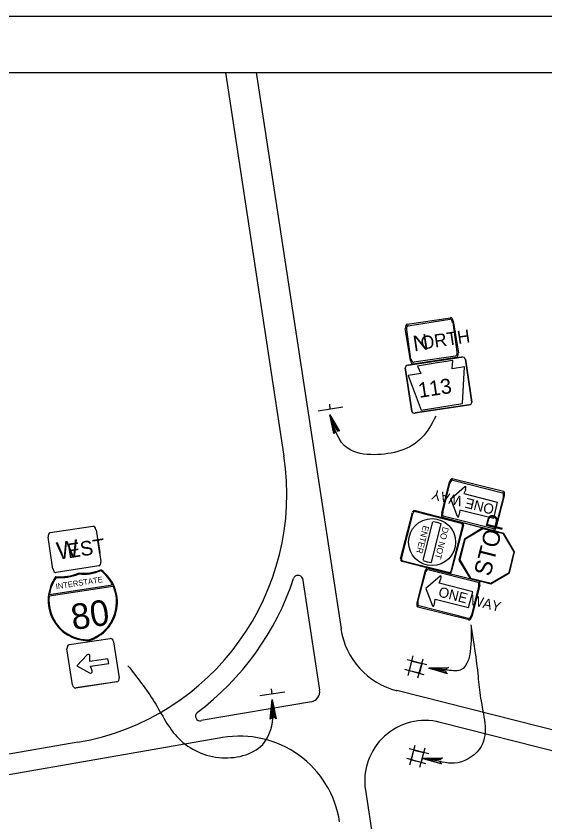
# Model space of a CAD drawing. Extents: x 640994 to 644422, y 298458 to 299646.
# Drawn here: x 642997.9 to 643138.7, y 299430.9 to 299645.6 of the extents above; entities that cross this region are included whole.
import ezdxf

# ---------------------------------------------------------------- set-up
doc = ezdxf.new("R2010")
doc.units = 0
for name, color, linetype in [('1', 7, 'Continuous'), ('2', 7, 'Continuous'), ('XCS-GRID-MIN', 7, 'Continuous')]:
    doc.layers.add(name, color=color, linetype=linetype)

msp = doc.modelspace()

# ---------------------------------------------------------------- linework, layer by layer
at = {"layer": '1'}
msp.add_line((642716.31, 299630.63), (643502.31, 299630.63), dxfattribs=at)
at = {"layer": '2'}
for p, q in [((643053.69, 299630.63), (643069.19, 299528.38)), ((643061.81, 299630.63), (643084.44, 299482.38)), ((643102.06, 299563.5), (643113.56, 299565.25)), ((643102.31, 299563.13), (643113.44, 299564.88)), ((643102.94, 299553.88), (643101.56, 299562.38)), ((643114.19, 299564), (643115.31, 299556.13)), ((643114.31, 299564.38), (643115.69, 299555.88)), ((643103.06, 299554.25), (643101.94, 299562.13)), ((643108.69, 299559.13), (643108.69, 299559.13)), ((643102.31, 299552.63), (643116.56, 299554.75)), ((643116.56, 299554.75), (643102.31, 299552.63)), ((643115.19, 299554.63), (643103.69, 299552.88)), ((643114.94, 299555), (643103.81, 299553.38)), ((643114.19, 299553.88), (643109.56, 299553.13)), ((643114.06, 299551.63), (643114.19, 299553.88)), ((643117.56, 299554.25), (643119.31, 299542.75)), ((643119.31, 299542.75), (643117.56, 299554.25)), ((643103.31, 299540.38), (643101.56, 299551.88)), ((643101.56, 299551.88), (643103.31, 299540.38)), ((643102.31, 299552.63), (643102.31, 299552.63)), ((643109.56, 299553.13), (643104.81, 299552.38)), ((643104.81, 299552.38), (643105.69, 299550.38)), ((643117.31, 299552.13), (643114.06, 299551.63)), ((643116.81, 299542.38), (643117.31, 299552.13)), ((643105.69, 299550.38), (643102.31, 299549.88)), ((643102.31, 299549.88), (643105.81, 299540.63)), ((643110.44, 299547.25), (643110.44, 299547.25)), ((643110.44, 299547.25), (643110.44, 299547.25)), ((643084.94, 299541.38), (643078.31, 299540.38)), ((643081.56, 299540.88), (643081.44, 299542.25)), ((643118.56, 299542), (643104.19, 299539.88)), ((643104.19, 299539.88), (643118.56, 299542)), ((643105.81, 299540.63), (643116.81, 299542.38)), ((643114.06, 299522.38), (643127.69, 299519)), ((643114.19, 299522), (643127.44, 299518.63)), ((643111.31, 299513.13), (643113.31, 299521.5)), ((643111.56, 299513.38), (643113.44, 299521.13)), ((643113.69, 299517), (643117.44, 299520.25)), ((643117.69, 299519.5), (643117.19, 299518.38)), ((643117.19, 299518.38), (643126.06, 299516.13)), ((643127.69, 299517.5), (643125.69, 299509.75)), ((643127.94, 299517.75), (643125.81, 299509.5)), ((643115.44, 299512.25), (643113.69, 299517)), ((643119.56, 299515.5), (643119.56, 299515.5)), ((643126.06, 299516.13), (643125.06, 299511.75)), ((643100.31, 299501), (643103.44, 299513.38)), ((643100.56, 299501), (643103.69, 299513.25)), ((643104.19, 299513.88), (643116.69, 299510.63)), ((643104.31, 299513.63), (643116.44, 299510.5)), ((643116.06, 299514), (643115.94, 299512.88)), ((643125.06, 299511.75), (643116.06, 299514)), ((643106.31, 299500.63), (643108.94, 299510.88)), ((643125.06, 299508.5), (643111.44, 299512)), ((643125.06, 299509), (643111.69, 299512.38)), ((643006.94, 299508), (643018.31, 299509.75)), ((643019.19, 299508.75), (643020.44, 299500.25)), ((643111.06, 299510.38), (643108.44, 299500)), ((643116.81, 299509.88), (643113.69, 299497.75)), ((643117.06, 299510), (643113.81, 299497.5)), ((643007.69, 299498.25), (643006.44, 299506.75)), ((643108.69, 299505.5), (643108.69, 299505.5)), ((643013.44, 299503.5), (643013.44, 299503.5)), ((643113.19, 299497.13), (643100.69, 299500.25)), ((643113.06, 299497.38), (643100.94, 299500.38)), ((643123.31, 299501.75), (643123.31, 299501.75)), ((643019.94, 299499.13), (643008.56, 299497.38)), ((643107.56, 299498.5), (643121.19, 299495.13)), ((643107.56, 299498.13), (643120.94, 299494.75)), ((643008.56, 299496), (643008.56, 299496)), ((643014.56, 299497), (643014.56, 299497)), ((643020.44, 299497.88), (643020.44, 299497.88)), ((643074.19, 299495.88), (643078.69, 299466)), ((643104.69, 299489.25), (643106.81, 299497.63)), ((643104.94, 299489.63), (643106.94, 299497.25)), ((643110.81, 299496.38), (643107.06, 299493.13)), ((643023.56, 299494), (643006.69, 299491.38)), ((643006.69, 299491.13), (643023.69, 299493.75)), ((643110.56, 299494.5), (643111.06, 299495.63)), ((643119.56, 299492.25), (643110.56, 299494.5)), ((643121.06, 299493.63), (643119.19, 299486)), ((643121.44, 299494), (643119.31, 299485.63)), ((643107.06, 299493.13), (643108.81, 299488.5)), ((643113.06, 299491.63), (643113.06, 299491.63)), ((643113.06, 299491.63), (643113.06, 299491.63)), ((643118.44, 299488), (643119.56, 299492.25)), ((643109.31, 299489), (643109.56, 299490.25)), ((643109.56, 299490.25), (643118.44, 299488)), ((643015.81, 299488.25), (643015.81, 299488.25)), ((643118.56, 299484.75), (643104.94, 299488.13)), ((643118.44, 299485.13), (643105.19, 299488.5)), ((643012.06, 299478.13), (643022.94, 299479.75)), ((643012.06, 299478.13), (643022.94, 299479.75)), ((643012.06, 299478.13), (643022.94, 299479.75)), ((643023.81, 299478.88), (643025.31, 299469.25)), ((643023.81, 299478.88), (643025.31, 299469.25)), ((643023.81, 299478.88), (643025.31, 299469.25)), ((643012.94, 299467.38), (643011.44, 299477)), ((643012.94, 299467.38), (643011.44, 299477)), ((643012.94, 299467.38), (643011.44, 299477)), ((643016.81, 299475.38), (643014.06, 299472.5)), ((643017.56, 299473.63), (643017.56, 299475.13)), ((643022.31, 299474.38), (643017.56, 299473.63)), ((643022.56, 299473.13), (643022.31, 299474.38)), ((643102.31, 299469.88), (643103.69, 299475.13)), ((643104.94, 299469.25), (643106.31, 299474.38)), ((643014.06, 299472.5), (643017.44, 299470.63)), ((643017.69, 299472.38), (643022.56, 299473.13)), ((643018.19, 299471.13), (643017.69, 299472.38)), ((643018.44, 299473.13), (643018.44, 299473.13)), ((643107.31, 299472.75), (643102.06, 299474.13)), ((643106.56, 299470.13), (643101.44, 299471.5)), ((643024.69, 299468.25), (643013.81, 299466.63)), ((643024.69, 299468.25), (643013.81, 299466.63)), ((643024.69, 299468.25), (643013.81, 299466.5)), ((643066.06, 299465), (643065.94, 299466.38)), ((643244.81, 299429), (643099.31, 299465.88)), ((643069.44, 299465.5), (643062.81, 299464.5)), ((643076.56, 299462.88), (643047.19, 299457.88)), ((643284.81, 299413.38), (643110.81, 299457.38)), ((643052.94, 299453.38), (642815.06, 299412)), ((643014.31, 299452.13), (642808.19, 299416.25)), ((643102.81, 299446.13), (643104.19, 299451.38)), ((643107.81, 299449), (643102.56, 299450.38)), ((643105.44, 299445.5), (643106.81, 299450.63)), ((643107.06, 299446.38), (643101.94, 299447.75)), ((643090.94, 299439.38), (643101.94, 299367))]:
    msp.add_line(p, q, dxfattribs=at)
for points in [[(643082.69, 299534.63), (643082.94, 299535), (643081.44, 299539.38), (643082.69, 299534.63), (643082.56, 299534.38), (643081.44, 299539.38), (643083.44, 299535.13), (643083.81, 299535.13), (643081.44, 299539.38), (643084.06, 299535), (643083.81, 299535.13)], [(643124.31, 299494.38), (643129.31, 299497.25), (643130.69, 299502.88), (643127.81, 299507.75), (643122.19, 299509.25), (643117.31, 299506.25), (643115.81, 299500.63), (643118.81, 299495.75), (643124.31, 299494.38)], [(643124.31, 299494.5), (643129.19, 299497.38), (643130.56, 299502.88), (643127.69, 299507.63), (643122.19, 299509), (643117.44, 299506.13), (643116.06, 299500.75), (643118.94, 299495.88), (643124.44, 299494.5)], [(643112.56, 299470.63), (643112.44, 299471), (643107.81, 299471.88), (643112.56, 299470.63), (643112.81, 299470.38), (643107.81, 299471.88), (643112.56, 299471.5), (643112.69, 299471.88), (643107.81, 299471.88), (643113.06, 299472), (643112.69, 299471.88)], [(643065.81, 299458.5), (643066.06, 299458.75), (643066.06, 299463.5), (643065.81, 299458.5), (643065.56, 299458.25), (643066.06, 299463.5), (643066.56, 299458.75), (643066.94, 299458.63), (643066.06, 299463.5), (643067.19, 299458.38), (643066.94, 299458.63)], [(643111.06, 299446.5), (643110.94, 299447), (643106.19, 299447.75), (643111.06, 299446.5), (643111.19, 299446.38), (643106.19, 299447.75), (643110.94, 299447.5), (643111.19, 299447.75), (643106.19, 299447.75), (643111.44, 299448), (643111.19, 299447.75)]]:
    msp.add_lwpolyline(points, dxfattribs=at)
for points in [[(643103.31, 299473.75), (643105.94, 299473.13), (643105.31, 299470.5), (643102.69, 299471.13)], [(643103.81, 299450), (643106.44, 299449.38), (643105.81, 299446.75), (643103.19, 299447.38)]]:
    msp.add_lwpolyline(points, close=True, dxfattribs=at)
msp.add_circle((643108.7, 299505.46), 6.26, dxfattribs=at)
for centre, radius, start, end in [((643002.81, 299518.3), 67.19, 279.8697, 8.6538), ((643104.02, 299513.28), 0.559, 75.7794, 165.7794), ((643104.14, 299513.08), 0.517, 75.7794, 165.7794), ((643108.69, 299505.41), 5.45, 64.3582, 87.2006), ((643116.29, 299510), 0.517, 345.7794, 75.7794), ((643116.49, 299510.12), 0.559, 345.7794, 75.7794), ((643100.87, 299500.82), 0.559, 165.7794, 255.7794), ((643101.07, 299500.94), 0.517, 165.7794, 255.7794), ((643108.72, 299505.51), 5.45, 244.3582, 267.2006), ((643015.69, 299509.47), 12.33, 264.4038, 292.9038), ((643014.13, 299489.46), 10.73, 286.7839, 53.6538), ((643017.13, 299489.92), 10.73, 143.6538, 270.5237), ((643017.13, 299489.92), 10.51, 144.3462, 171.8611), ((643009.69, 299508.55), 12.33, 264.4038, 292.9038), ((643009.69, 299508.55), 12.56, 264.9943, 292.6428), ((643015.69, 299509.47), 12.56, 264.6648, 292.3133), ((643014.13, 299489.46), 10.51, 25.4466, 52.9614), ((643002.81, 299518.3), 72.56, 306.6068, 341.9288), ((643073, 299495.29), 1.31, 24.3383, 157.5626), ((643113.21, 299497.86), 0.517, 255.7794, 345.7794), ((643113.33, 299497.66), 0.559, 255.7794, 345.7794), ((643014.13, 299489.46), 10.51, 286.7839, 24.1669), ((643017.13, 299489.92), 10.51, 173.1407, 270.5237), ((643104.32, 299485.4), 20.16, 188.6538, 255.7794), ((643017.1, 299475.09), 0.46, 356.9014, 140.8081), ((643017.71, 299470.97), 0.46, 238.5129, 19.1785), ((643076.07, 299465.58), 2.69, 279.8696, 8.6536), ((643046.97, 299459.1), 1.3, 133.1831, 281.0673), ((643106.88, 299441.78), 16.13, 75.7793, 188.6538), ((643057.5, 299426.88), 26.88, 8.6538, 99.8697)]:
    msp.add_arc(centre, radius, start, end, dxfattribs=at)
for centre, major_axis, ratio, start_param, end_param in [((643113.58, 299563.89), (-0.15, 0.983), 0.6, 4.712389, 6.283185), ((643113.72, 299564.23), (-0.16, 1.06), 0.6, 4.712389, 6.283185), ((643102.25, 299562.48), (0.16, -1.06), 0.6, 3.141593, 4.712389), ((643102.48, 299562.2), (0.15, -0.983), 0.6, 3.141593, 4.712389), ((643114.78, 299556.02), (-0.15, 0.983), 0.6, 3.141593, 4.712389), ((643103.54, 299553.98), (0.16, -1.06), 0.6, 4.712389, 6.283185), ((643103.68, 299554.33), (0.15, -0.983), 0.6, 4.712389, 6.283185), ((643115.02, 299555.73), (-0.16, 1.06), 0.6, 3.141593, 4.712389), ((643116.71, 299554.12), (-0.797, -0.121), 0.8, 3.141593, 4.712389), ((643116.71, 299554.12), (-0.797, -0.121), 0.8, 3.141593, 4.712389), ((643102.36, 299551.94), (-0.797, -0.121), 0.8, 4.712389, 6.283185), ((643102.36, 299551.94), (-0.797, -0.121), 0.8, 4.712389, 6.283185), ((643118.46, 299542.64), (0.797, 0.121), 0.8, 4.712389, 6.283185), ((643118.46, 299542.64), (0.797, 0.121), 0.8, 4.712389, 6.283185), ((643104.11, 299540.46), (0.797, 0.121), 0.8, 3.141593, 4.712389), ((643104.11, 299540.46), (0.797, 0.121), 0.8, 3.141593, 4.712389), ((643113.86, 299521.35), (-0.26, -1.04), 0.4667, 3.141593, 4.712389), ((643113.92, 299521.01), (-0.244, -0.964), 0.4667, 3.141593, 4.712389), ((643117.43, 299519.73), (0.142, 0.56), 0.4667, 4.423888, 6.899163), ((643127.25, 299517.63), (0.244, 0.964), 0.4667, 4.712389, 6.283185), ((643127.48, 299517.9), (0.26, 1.04), 0.4667, 4.712389, 6.283185), ((643111.75, 299513.02), (-0.26, -1.04), 0.4667, 4.712389, 6.283185), ((643111.97, 299513.29), (-0.244, -0.964), 0.4667, 4.712389, 6.283185), ((643115.66, 299512.73), (0.142, 0.56), 0.4667, 2.525615, 5.00089), ((643018.53, 299508.64), (-0.16, 1.06), 0.6, 4.712389, 6.283185), ((643125.3, 299509.91), (0.244, 0.964), 0.4667, 3.141593, 4.712389), ((643125.36, 299509.56), (0.26, 1.04), 0.4667, 3.141593, 4.712389), ((643007.05, 299506.9), (0.16, -1.06), 0.6, 3.141593, 4.712389), ((643019.82, 299500.14), (-0.16, 1.06), 0.6, 3.141593, 4.712389), ((643008.35, 299498.39), (0.16, -1.06), 0.6, 4.712389, 6.283185), ((643107.27, 299497.52), (-0.26, -1.04), 0.4667, 3.141593, 4.712389), ((643107.34, 299497.17), (-0.244, -0.964), 0.4667, 3.141593, 4.712389), ((643110.85, 299495.91), (0.142, 0.56), 0.4667, 4.423888, 6.899163), ((643120.67, 299493.8), (0.244, 0.964), 0.4667, 4.712389, 6.283185), ((643120.89, 299494.07), (0.26, 1.04), 0.4667, 4.712389, 6.283185), ((643105.38, 299489.45), (-0.244, -0.964), 0.4667, 4.712389, 6.283185), ((643105.16, 299489.18), (-0.26, -1.04), 0.4667, 4.712389, 6.283185), ((643109.07, 299488.91), (0.142, 0.56), 0.4667, 2.525615, 5.00089), ((643118.71, 299486.08), (0.244, 0.964), 0.4667, 3.141593, 4.712389), ((643118.78, 299485.73), (0.26, 1.04), 0.4667, 3.141593, 4.712389), ((643023.14, 299478.83), (-0.14, 0.921), 0.769266, 4.712389, 6.283185), ((643023.14, 299478.83), (-0.14, 0.921), 0.769266, 4.712389, 6.283185), ((643023.14, 299478.83), (-0.14, 0.921), 0.769266, 4.712389, 6.283185), ((643012.15, 299477.16), (0.14, -0.921), 0.769266, 3.141593, 4.712389), ((643012.15, 299477.16), (0.14, -0.921), 0.769266, 3.141593, 4.712389), ((643012.15, 299477.16), (0.14, -0.921), 0.769266, 3.141593, 4.712389), ((643024.61, 299469.16), (-0.14, 0.921), 0.769266, 3.141593, 4.712389), ((643024.61, 299469.16), (-0.14, 0.921), 0.769266, 3.141593, 4.712389), ((643024.61, 299469.16), (-0.14, 0.921), 0.769266, 3.141593, 4.712389), ((643013.62, 299467.49), (0.14, -0.921), 0.769266, 4.712389, 6.283185), ((643013.62, 299467.49), (0.14, -0.921), 0.769266, 4.712389, 6.283185), ((643013.62, 299467.49), (0.14, -0.921), 0.769266, 4.712389, 6.283185)]:
    msp.add_ellipse(centre, major_axis=major_axis, ratio=ratio, start_param=start_param, end_param=end_param, dxfattribs=at)
for points in [[(643109.69, 299539), (643106.06, 299533.38), (643093.31, 299528.75), (643086.31, 299530.38), (643081.44, 299539.38)], [(643119.06, 299483.38), (643120.94, 299469.67), (643121.61, 299463.86), (643121.79, 299451.02), (643115.55, 299446.66), (643108.81, 299447.5)], [(643119.06, 299483.38), (643119.06, 299478.38), (643116.22, 299471.37), (643112.31, 299471.38), (643110.17, 299471.43)], [(643027.69, 299472.5), (643034.69, 299462.88), (643041.19, 299453.13), (643052.69, 299448), (643064.06, 299452.13), (643066.31, 299459.38), (643066.06, 299463.5)]]:
    msp.add_spline(points, degree=3, dxfattribs=at)
at = {"layer": 'XCS-GRID-MIN'}
msp.add_lwpolyline([(642676.31, 299645.63), (643517.31, 299645.63), (643517.31, 299051.63), (642676.31, 299051.63)], close=True, dxfattribs=at)

# ---------------------------------------------------------------- texts
at = {"layer": '2'}
for s, height, rotation, p in [('N', 4.16, 8.6525, (643103.94, 299556.25)), ('ORTH', 3.487, 8.6538, (643105.94, 299556.75)), ('113', 4, 8.6536, (643105.31, 299543.88)), ('ONE WAY', 2.687, 165.779, (643125.44, 299515.38)), ('STOP', 4.541, 75.7795, (643124.19, 299496.13)), ('ENTER', 1.677, 255.781, (643106.31, 299510)), ('DO NOT', 1.677, 255.7793, (643111.56, 299509.63)), ('W', 4.63, 8.6525, (643009.06, 299500.75)), ('EST', 3.875, 8.6538, (643011.81, 299501.13)), ('INTERSTATE', 1.517, 8.6538, (643008.56, 299492.88)), ('ONE WAY', 2.687, 345.779, (643110.19, 299491)), ('80', 6.829, 8.6538, (643013.06, 299482))]:
    msp.add_text(s, height=height, rotation=rotation, dxfattribs=at).set_placement(p)

doc.saveas('drawing.dxf')
